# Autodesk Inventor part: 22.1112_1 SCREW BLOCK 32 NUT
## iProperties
Created: 2007-04
Part Number: 22.1112_1 SCREW BLOCK 32 NUT
Material: Steel
Document SubType Name: Modeling
Designer: Andy Moles
Density: 7.85 g/cm^3
Author: Andy Moles
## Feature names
1. Extrusion1
